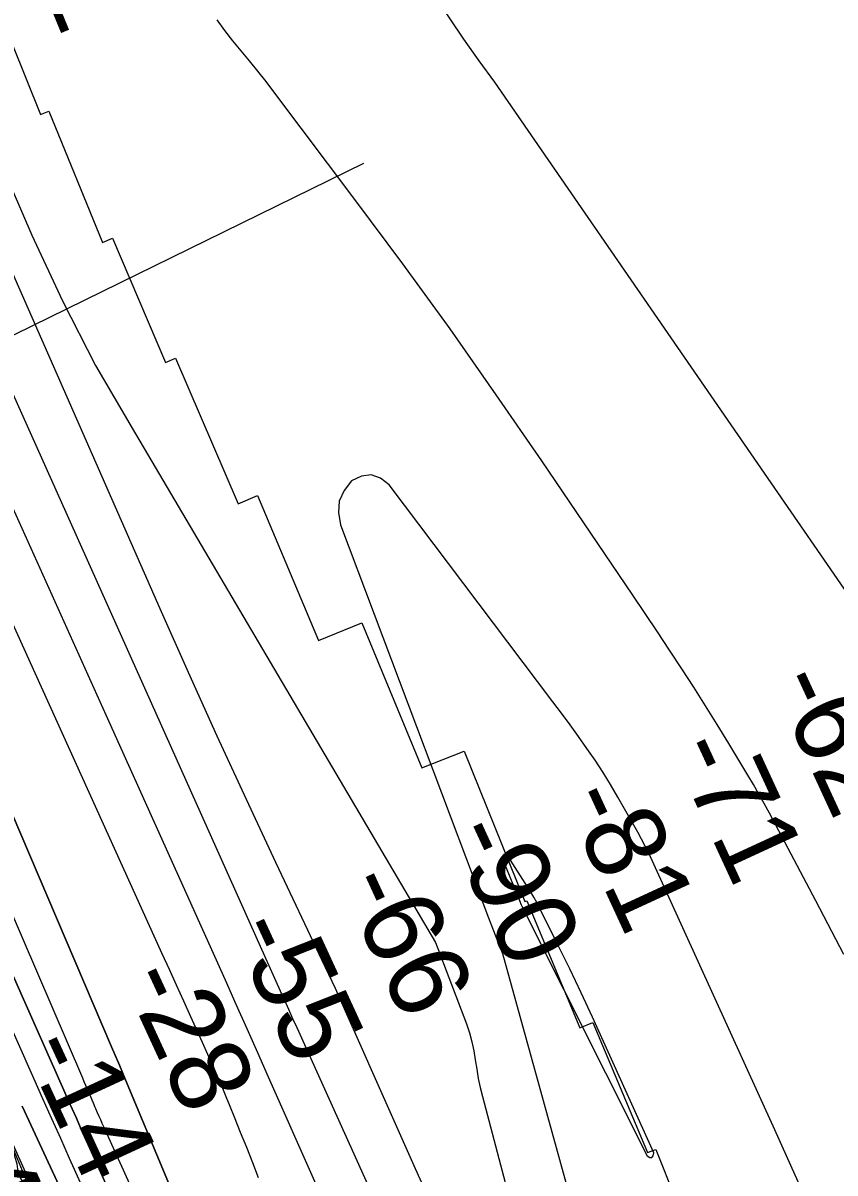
# Model space of a CAD drawing. Extents: x 3424494 to 3462436, y 522220 to 547718.
# Drawn here: x 3439589 to 3440272, y 541553 to 542520 of the extents above; entities that cross this region are included whole.
import ezdxf

# ---------------------------------------------------------------- set-up
doc = ezdxf.new("R2010")
doc.units = 0
for name, color, linetype in [('V-RIVR-EDGE', 7, 'Continuous'), ('V-RIVR-RANG', 7, 'Continuous'), ('V-RRAP-RVMT', 7, 'Continuous'), ('V-TOPO-DPTH', 7, 'Continuous'), ('V-TOPO-MAJR', 7, 'Continuous'), ('V-TOPO-MINR', 7, 'Continuous'), ('V-TOPO-WATR', 7, 'Continuous')]:
    doc.layers.add(name, color=color, linetype=linetype)

msp = doc.modelspace()

# ---------------------------------------------------------------- linework, layer by layer
at = {"layer": 'V-RIVR-EDGE'}
msp.add_spline([(3438393.42, 545837.57), (3438393.61, 545836.87), (3438395.05, 545831.39), (3438401.62, 545826.62), (3438403.8, 545821.13), (3438403.78, 545813.45), (3438405.22, 545801.75), (3438408.47, 545786.39), (3438409.18, 545777.98), (3438409.16, 545769.94), (3438409.49, 545757.14), (3438410.92, 545744.71), (3438420.29, 545688.76), (3438423.49, 545652.93), (3438428.86, 545606.12), (3438430.6, 545570.3), (3438432.37, 545549.09), (3438435.92, 545504.12), (3438439.16, 545485.47), (3438444.96, 545463.89), (3438449.31, 545451.81), (3438457.7, 545444.12), (3438458.06, 545439), (3438458.77, 545433.15), (3438463.52, 545430.21), (3438470.82, 545426.9), (3438472.63, 545421.41), (3438472.25, 545413.01), (3438471.11, 545394.73), (3438468.15, 545380.85), (3438467.77, 545375.37), (3438465.55, 545364.41), (3438464.78, 545351.25), (3438465.85, 545339.91), (3438471.67, 545328.93), (3438480.75, 545301.86), (3438480.71, 545287.24), (3438482.14, 545273.71), (3438487.22, 545257.98), (3438494.14, 545246.99), (3438498.87, 545239.31), (3438502.86, 545227.23), (3438508.27, 545196.51), (3438511.14, 545174.21), (3438523.44, 545123), (3438525.59, 545104.72), (3438525.57, 545098.14), (3438527.72, 545082.41), (3438530.97, 545064.86), (3438530.94, 545051.33), (3438530.54, 545038.91), (3438527.6, 545030.87), (3438526.84, 545021), (3438528.62, 545002.72), (3438527.46, 544975.67), (3438526.31, 544955.57), (3438524.81, 544938.76), (3438526.99, 544931.81), (3438537.92, 544918.26), (3438543.74, 544908.37), (3438545.55, 544899.23), (3438545.53, 544889.73), (3438542.56, 544875.11), (3438542.17, 544862.68), (3438543.62, 544857.2), (3438543.61, 544855), (3438540.68, 544850.62), (3438539.19, 544841.12), (3438540.25, 544827.23), (3438541.69, 544817.72), (3438544.95, 544805.29), (3438544.91, 544790.3), (3438543.39, 544767.27), (3438545.9, 544746.43), (3438547.7, 544732.9), (3438549.12, 544719.01), (3438553.49, 544712.42), (3438557.51, 544708.38), (3438557.13, 544706.19), (3438556.03, 544704.37), (3438550.91, 544701.46), (3438550.16, 544693.78), (3438554.49, 544672.57), (3438557.73, 544650.63), (3438563.14, 544620.27), (3438569.66, 544598.69), (3438581.95, 544543.1), (3438585.19, 544522.98), (3438584.79, 544506.53), (3438588.41, 544491.17), (3438594.94, 544472.51), (3438598.56, 544458.98), (3438598.51, 544439.6), (3438598.48, 544424.98), (3438598.08, 544411.82), (3438598.06, 544405.61), (3438599.51, 544397.56), (3438604.22, 544381.1), (3438610.37, 544356.96), (3438613.26, 544341.6), (3438619.09, 544333.18), (3438624.91, 544321.1), (3438628.15, 544301.72), (3438628.82, 544279.42), (3438634.99, 544260.03), (3438634.97, 544251.26), (3438637.85, 544233.34), (3438638.54, 544216.16), (3438645.09, 544204.08), (3438650.91, 544193.1), (3438650.88, 544182.13), (3438651.56, 544159.1), (3438651.54, 544153.25), (3438652.96, 544137.53), (3438657.32, 544123.99), (3438667.11, 544092.89), (3438672.9, 544069.49), (3438679.8, 544048.63), (3438680.49, 544035.47), (3438681.93, 544024.5), (3438680.45, 544017.19), (3438685.53, 544000.73), (3438686.94, 543981.72), (3438692.73, 543957.58), (3438693.77, 543933.08), (3438694.09, 543918.1), (3438698.07, 543900.54), (3438698.41, 543889.94), (3438698.4, 543885.55), (3438700.96, 543885.18), (3438708.64, 543887.72), (3438712.65, 543882.59), (3438718.45, 543864.67), (3438733.33, 543818.2), (3438741.31, 543793.69), (3438746.73, 543767.36), (3438753.96, 543734.08), (3438762.28, 543698.96), (3438770.98, 543671.53), (3438780.05, 543642.62), (3438782.94, 543630.92), (3438781.85, 543630.92), (3438771.24, 543630.22), (3438766.85, 543628.77), (3438765.74, 543622.56), (3438771.21, 543615.23), (3438777.02, 543602.42), (3438775.17, 543590), (3438778.8, 543582.31), (3438781.72, 543581.21), (3438785.75, 543582.3), (3438793.07, 543586.3), (3438797.82, 543584.82), (3438800.36, 543578.24), (3438805.76, 543546.06), (3438811.93, 543525.94), (3438819.53, 543497.04), (3438822.81, 543490.09), (3438824.62, 543484.96), (3438830.07, 543471.42), (3438839.89, 543450.93), (3438843.89, 543441.78), (3438850.42, 543423.85), (3438851.87, 543417.27), (3438850.75, 543408.13), (3438850.37, 543400.82), (3438855.08, 543386.19), (3438860.17, 543372.29), (3438866.73, 543366.06), (3438867.8, 543356.55), (3438867.78, 543347.78), (3438868.86, 543341.19), (3438880.52, 543326.91), (3438889.63, 543312.99), (3438898.72, 543293.96), (3438901.98, 543280.06), (3438905.96, 543265.07), (3438917.2, 543229.58), (3438923, 543209.46), (3438927.74, 543203.6), (3438932.81, 543185.68), (3438937.14, 543160.81), (3438942.56, 543134.84), (3438946.9, 543117.65), (3438946.88, 543110.34), (3438946.5, 543102.66), (3438951.23, 543091.69), (3438960.71, 543082.52), (3438961.42, 543076.67), (3438965.41, 543063.87), (3438966.48, 543053.26), (3438963.91, 543047.42), (3438962.07, 543042.67), (3438965.32, 543026.95), (3438970.39, 543005.37), (3438977.28, 542983.78), (3438982.74, 542973.9), (3438991.83, 542954.87), (3439000.92, 542934.01), (3439008.55, 542918.64), (3439023.85, 542895.57), (3439028.21, 542883.13), (3439036.95, 542873.24), (3439040.94, 542860.8), (3439048.21, 542843.6), (3439058.78, 542827.86), (3439070.41, 542802.61), (3439079.5, 542782.84), (3439082.38, 542763.46), (3439082.71, 542749.21), (3439081.58, 542735.32), (3439079.34, 542717.41), (3439078.96, 542710.47), (3439082.94, 542696.93), (3439086.21, 542687.79), (3439090.59, 542683.75), (3439099.36, 542684.1), (3439102.28, 542680.07), (3439104.09, 542676.04), (3439104.07, 542668.37), (3439104.05, 542657.4), (3439105.49, 542647.53), (3439106.2, 542642.04), (3439115.29, 542621.18), (3439129.13, 542598.85), (3439132.42, 542599.57), (3439141.52, 542584.2), (3439147.32, 542566.64), (3439154.59, 542546.88), (3439164.04, 542527.48), (3439169.85, 542510.65), (3439173.48, 542500.04), (3439177.48, 542490.89), (3439190.59, 542472.22), (3439206.25, 542447.32), (3439209.14, 542433.06), (3439211.31, 542426.84), (3439222.26, 542418.41), (3439225.9, 542411.82), (3439227.33, 542401.21), (3439229.88, 542396.09), (3439237.54, 542388.03), (3439240.44, 542378.88), (3439242.98, 542371.2), (3439252.8, 542351.07), (3439262.61, 542326.19), (3439271.71, 542310.81), (3439276.41, 542291.79), (3439280.39, 542275.33), (3439282.56, 542264.73), (3439280.36, 542261.08), (3439278.16, 542259.25), (3439283.24, 542243.89), (3439285.4, 542231.82), (3439293.05, 542221.2), (3439297.05, 542211.69), (3439308.34, 542194.48), (3439310.89, 542190.45), (3439316.37, 542190.07), (3439317.46, 542186.05), (3439322.88, 542161.54), (3439326.86, 542146.18), (3439328.66, 542133.38), (3439327.89, 542118.76), (3439331.14, 542099.74), (3439347.11, 542053.28), (3439351.81, 542035.36), (3439360.55, 542018.88), (3439371.1, 542000.58), (3439381.29, 541982.64), (3439394.06, 541973.11), (3439397.7, 541966.88), (3439399.87, 541955.55), (3439406.05, 541943.47), (3439414.79, 541930.65), (3439422.81, 541920.76), (3439437.76, 541904.64), (3439450.5, 541882.31), (3439460.66, 541852.68), (3439464.66, 541843.89), (3439468.29, 541833.28), (3439481.77, 541815.34), (3439490.14, 541800.7), (3439498.52, 541788.61), (3439505.07, 541778.36), (3439505.42, 541771.41), (3439505.75, 541754.6), (3439506.83, 541747.65), (3439515.2, 541733.74), (3439522.83, 541717.27), (3439531.22, 541708.84), (3439533.76, 541701.16), (3439533.73, 541689.83), (3439534.05, 541670.45), (3439534.03, 541662.04), (3439535.48, 541656.56), (3439543.49, 541645.21), (3439555.87, 541625.8), (3439565.7, 541607.5), (3439574.05, 541583.72), (3439582.77, 541562.5), (3439587.48, 541546.4), (3439591.86, 541542.73), (3439598.8, 541540.16), (3439601.35, 541536.5), (3439607.53, 541524.78), (3439631.54, 541476.84), (3439645.71, 541442.07), (3439652.62, 541429.63), (3439663.17, 541408.03), (3439674.84, 541397.77), (3439682.85, 541381.3)], degree=3, dxfattribs=at)
at = {"layer": 'V-RIVR-RANG'}
msp.add_line((3439066.77, 542005.95), (3439875.11, 542401.67), dxfattribs=at)
at = {"layer": 'V-RRAP-RVMT'}
for p, q in [((3439555.73, 542560.35), (3439603.3, 542442.57)), ((3439603.3, 542442.57), (3439610.28, 542445.43)), ((3439610.28, 542445.43), (3439655.36, 542335.12)), ((3439655.36, 542335.12), (3439663.78, 542338.74)), ((3439663.78, 542338.74), (3439708.37, 542234.04)), ((3439708.37, 542234.04), (3439716.94, 542237.76)), ((3439716.94, 542237.76), (3439769.46, 542115.4)), ((3439769.46, 542115.4), (3439785.79, 542122.26)), ((3439785.79, 542122.26), (3439836.99, 542000.35)), ((3439836.99, 542000.35), (3439873.48, 542015.35)), ((3439873.48, 542015.35), (3439924.08, 541893.3)), ((3439924.08, 541893.3), (3439959.51, 541907.54)), ((3439959.51, 541907.54), (3440010.74, 541781.03)), ((3440010.74, 541781.03), (3440012.41, 541781.71)), ((3440012.41, 541781.71), (3440056.78, 541674.78)), ((3440056.78, 541674.78), (3440067.86, 541679.46)), ((3440067.86, 541679.46), (3440113.85, 541569.92)), ((3439620.44, 541476.79), (3439574.23, 541588.12)), ((3440113.85, 541569.92), (3440120.69, 541572.65)), ((3440120.69, 541572.65), (3440177.07, 541432.82))]:
    msp.add_line(p, q, dxfattribs=at)
at = {"layer": 'V-TOPO-DPTH'}
for points in [[(3439387.23, 542438.94), (3439705.43, 541737.4), (3439711.45, 541724.14), (3439717.46, 541710.88), (3439723.47, 541697.62), (3439729.48, 541684.36), (3439739.23, 541662.86), (3439740.37, 541660.35), (3439741.5, 541657.84), (3439742.62, 541655.32), (3439743.74, 541652.81), (3439748.67, 541641.65), (3439752.21, 541633.54), (3439755.71, 541625.41), (3439759.13, 541617.24), (3439762.5, 541609.06), (3439766.17, 541600), (3439771.31, 541587.26), (3439776.41, 541574.5), (3439781.45, 541561.71), (3439786.45, 541548.91)], [(3439387.23, 542438.94), (3439705.43, 541737.4), (3439711.45, 541724.14), (3439717.46, 541710.88), (3439723.47, 541697.62), (3439729.48, 541684.36), (3439739.23, 541662.86), (3439740.37, 541660.35), (3439741.5, 541657.84), (3439742.62, 541655.32), (3439743.74, 541652.81), (3439748.67, 541641.65), (3439752.21, 541633.54), (3439755.71, 541625.41), (3439759.13, 541617.24), (3439762.5, 541609.06), (3439766.17, 541600), (3439771.31, 541587.26), (3439776.41, 541574.5), (3439781.45, 541561.71), (3439786.45, 541548.91)], [(3439834.98, 541543.11), (3439795.07, 541633.34), (3439786.04, 541653.73), (3439776.97, 541674.1), (3439767.87, 541694.45), (3439758.74, 541714.79), (3439658.36, 541937.8), (3439618.08, 542027.35), (3439577.86, 542116.92)], [(3439834.98, 541543.11), (3439795.07, 541633.34), (3439786.04, 541653.73), (3439776.97, 541674.1), (3439767.87, 541694.45), (3439758.74, 541714.79), (3439658.36, 541937.8), (3439618.08, 542027.35), (3439577.86, 542116.92)], [(3439422.76, 542073.46), (3439622.83, 541622.5), (3439626.34, 541614.59), (3439629.88, 541606.69), (3439633.42, 541598.79), (3439636.98, 541590.89), (3439795.13, 541241.12)], [(3439795.13, 541241.12), (3439636.98, 541590.89), (3439633.42, 541598.79), (3439629.88, 541606.69), (3439626.34, 541614.59), (3439622.83, 541622.5), (3439422.76, 542073.46)], [(3439750.53, 541450.72), (3439731.83, 541494.97), (3439713.23, 541539.26), (3439689.15, 541596.86), (3439682.65, 541612.38), (3439676.12, 541627.88), (3439669.57, 541643.38), (3439662.99, 541658.86), (3439571.38, 541873.92)], [(3439750.53, 541450.72), (3439731.83, 541494.97), (3439713.23, 541539.26), (3439689.15, 541596.86), (3439682.65, 541612.38), (3439676.12, 541627.88), (3439669.57, 541643.38), (3439662.99, 541658.86), (3439571.38, 541873.92)], [(3439587.71, 541608.96), (3439970.51, 540785.55), (3440067.12, 540601.4), (3440170.5, 540405.32), (3440401.09, 540001.18), (3440433.34, 539960.23), (3440699.8, 539603.68)], [(3440699.8, 539603.68), (3440433.34, 539960.23), (3440401.09, 540001.18), (3440170.5, 540405.32), (3440067.12, 540601.4), (3439970.51, 540785.55), (3439587.71, 541608.96)]]:
    msp.add_lwpolyline(points, dxfattribs=at)
at = {"layer": 'V-TOPO-MAJR'}
msp.add_lwpolyline([(3439976.95, 541325.22), (3439819.03, 541674.84), (3439815.57, 541682.52), (3439812.11, 541690.2), (3439808.65, 541697.88), (3439805.2, 541705.56), (3439550, 542274.38)], dxfattribs=at)
at = {"layer": 'V-TOPO-MINR'}
for points in [[(3440604.17, 541500.05), (3440552.26, 541586.74), (3440501.13, 541673.9), (3440450.52, 541761.35), (3440362.52, 541914.96), (3440356.33, 541925.87), (3440350.21, 541936.81), (3440344.17, 541947.81), (3440338.2, 541958.84), (3439985.47, 542469.75), (3439972.08, 542487.68), (3439959.2, 542506.02), (3439891.43, 542607.1)], [(3440278.92, 541736.51), (3440255.3, 541781.57), (3440216.34, 541855.27), (3440211.98, 541863.35), (3440207.53, 541871.39), (3440202.94, 541879.36), (3440198.27, 541887.27), (3440182.18, 541913.98), (3440172.51, 541929.82), (3440162.72, 541945.58), (3440152.74, 541961.22), (3440142.63, 541976.78), (3440132.4, 541992.27), (3440122.13, 542007.73), (3440111.8, 542023.14), (3440101.42, 542038.52), (3440024.9, 542151.44), (3439986.57, 542207.1), (3439947.69, 542262.37), (3439907.98, 542317.03), (3439867.71, 542371.31), (3439799.63, 542461.63), (3439792.92, 542470.39), (3439786.12, 542479.08), (3439779.17, 542487.65), (3439772.14, 542496.16), (3439765.16, 542504.7), (3439758.34, 542513.36), (3439751.75, 542522.2)], [(3439529.51, 542494.66), (3439595.99, 542341.23), (3439621.81, 542285.89), (3439649.59, 542231.62), (3439680.32, 542178.96), (3439935.37, 541746.69), (3439938.85, 541737.87), (3439942.26, 541729.02), (3439961.46, 541678.11), (3439963.96, 541670.69), (3439966.11, 541663.18), (3439967.73, 541655.54), (3439968.99, 541647.81), (3439970.14, 541640.04), (3439971.49, 541632.31), (3439973.14, 541624.65), (3439975, 541617.02), (3440006.55, 541497.95)], [(3439514.46, 542457.25), (3439703.62, 542027.32), (3439727.45, 541973.77), (3439751.59, 541920.35), (3439776.17, 541867.15), (3439801.05, 541814.08), (3439840.02, 541731.85), (3439845.59, 541719.97), (3439851.1, 541708.07), (3439856.5, 541696.11), (3439861.84, 541684.13), (3439884.69, 541632.23), (3439901.49, 541594.32), (3439918.43, 541556.47), (3439935.56, 541518.7)], [(3439387.23, 542438.94), (3439705.43, 541737.4), (3439711.45, 541724.14), (3439717.46, 541710.88), (3439723.47, 541697.62), (3439729.48, 541684.36), (3439739.23, 541662.86), (3439740.37, 541660.35), (3439741.5, 541657.84), (3439742.62, 541655.32), (3439743.74, 541652.81), (3439748.67, 541641.65), (3439752.21, 541633.54), (3439755.71, 541625.41), (3439759.13, 541617.24), (3439762.5, 541609.06), (3439766.17, 541600), (3439771.31, 541587.26), (3439776.41, 541574.5), (3439781.45, 541561.71), (3439786.45, 541548.91)], [(3439322.72, 542366.68), (3439638.5, 541632.93), (3439639.83, 541629.82), (3439641.16, 541626.72), (3439642.48, 541623.61), (3439643.8, 541620.5), (3439646.07, 541615.12), (3439646.42, 541614.27), (3439647.43, 541611.86), (3439648.97, 541608.24), (3439649.49, 541607.04), (3439651.02, 541603.57), (3439652.31, 541600.64), (3439653.61, 541597.71), (3439654.92, 541594.78), (3439656.24, 541591.86), (3439892.9, 541070.5)], [(3439343.14, 542204.97), (3439597.57, 541632.05), (3439605, 541615.37), (3439612.45, 541598.7), (3439619.94, 541582.04), (3439627.45, 541565.4), (3439702.4, 541399.73)], [(3440254.1, 541515.54), (3440220.81, 541588.97), (3440117.68, 541815.64), (3440114.86, 541821.64), (3440111.93, 541827.58), (3440108.84, 541833.45), (3440105.65, 541839.26), (3440088.92, 541868.79), (3440082.77, 541879.27), (3440076.41, 541889.61), (3440069.75, 541899.76), (3440062.88, 541909.78), (3440055.81, 541919.67), (3440048.68, 541929.51), (3440041.46, 541939.28), (3440034.18, 541949.02), (3439896.55, 542131.26), (3439889.17, 542136.89), (3439881.49, 542139.79), (3439873.37, 542138.57), (3439864.97, 542134.62), (3439858.55, 542126.43), (3439854.46, 542117.64), (3439853.85, 542107.97), (3439855.57, 542097.7), (3439968.73, 541797.2), (3439974.43, 541782.19), (3439980.19, 541767.21), (3439986.03, 541752.26), (3439991.92, 541737.33), (3440139.58, 541203.45)], [(3439834.98, 541543.11), (3439795.07, 541633.34), (3439786.04, 541653.73), (3439776.97, 541674.1), (3439767.87, 541694.45), (3439758.74, 541714.79), (3439658.36, 541937.8), (3439618.08, 542027.35), (3439577.86, 542116.92)], [(3439422.76, 542073.46), (3439622.83, 541622.5), (3439626.34, 541614.59), (3439629.88, 541606.69), (3439633.42, 541598.79), (3439636.98, 541590.89), (3439795.13, 541241.12)], [(3439571.38, 541873.92), (3439662.99, 541658.86), (3439669.57, 541643.38), (3439676.12, 541627.88), (3439682.65, 541612.38), (3439689.15, 541596.86), (3439713.23, 541539.26), (3439731.83, 541494.97), (3439750.53, 541450.72)], [(3439995.17, 541819.87), (3439994.3, 541819.8), (3439993.37, 541819.44), (3439992.65, 541818.6), (3439992.19, 541817.7), (3439992.12, 541816.68), (3439992.31, 541815.6), (3440006, 541781.81), (3440007.52, 541778.37), (3440008.07, 541777.24), (3440113.46, 541567.19), (3440115.77, 541565.94), (3440117.56, 541565.79), (3440118.56, 541567.27), (3440119.05, 541569.85), (3440076.93, 541663.39), (3440067.59, 541683.82), (3440058.1, 541704.16), (3440048.37, 541724.4), (3440038.48, 541744.56), (3440023, 541775.67), (3440020.66, 541780.18), (3440018.23, 541784.63), (3440015.66, 541789.01), (3440013, 541793.33), (3439996.71, 541818.84), (3439995.17, 541819.87)], [(3439577.33, 541582.6), (3439592.76, 541548.26)]]:
    msp.add_lwpolyline(points, dxfattribs=at)
at = {"layer": 'V-TOPO-WATR'}
msp.add_lwpolyline([(3440699.8, 539603.68), (3440433.34, 539960.23), (3440401.09, 540001.18), (3440170.5, 540405.32), (3440067.12, 540601.4), (3439970.51, 540785.55), (3439587.71, 541608.96)], dxfattribs=at)

# ---------------------------------------------------------------- texts
at = {"layer": 'V-RIVR-RANG'}
for s, rotation, p in [('-72', 292.30539, (3439573.12, 542626.77)), ('-62', 294.76308, (3440217.61, 541965.02)), ('-71', 294.76308, (3440133.44, 541908.75)), ('-81', 294.76308, (3440042.31, 541867.56)), ('-90', 294.76308, (3439945.66, 541838.36)), ('-66', 294.76308, (3439855.08, 541795.98)), ('-55', 294.76308, (3439762.63, 541757.67)), ('-28', 294.76308, (3439671.72, 541716.01)), ('12.4', 294.47833, (3439475.01, 541666.37)), ('-14', 294.76308, (3439588.21, 541658.3))]:
    msp.add_text(s, height=67, rotation=rotation, dxfattribs=at).set_placement(p)

doc.saveas('drawing.dxf')
